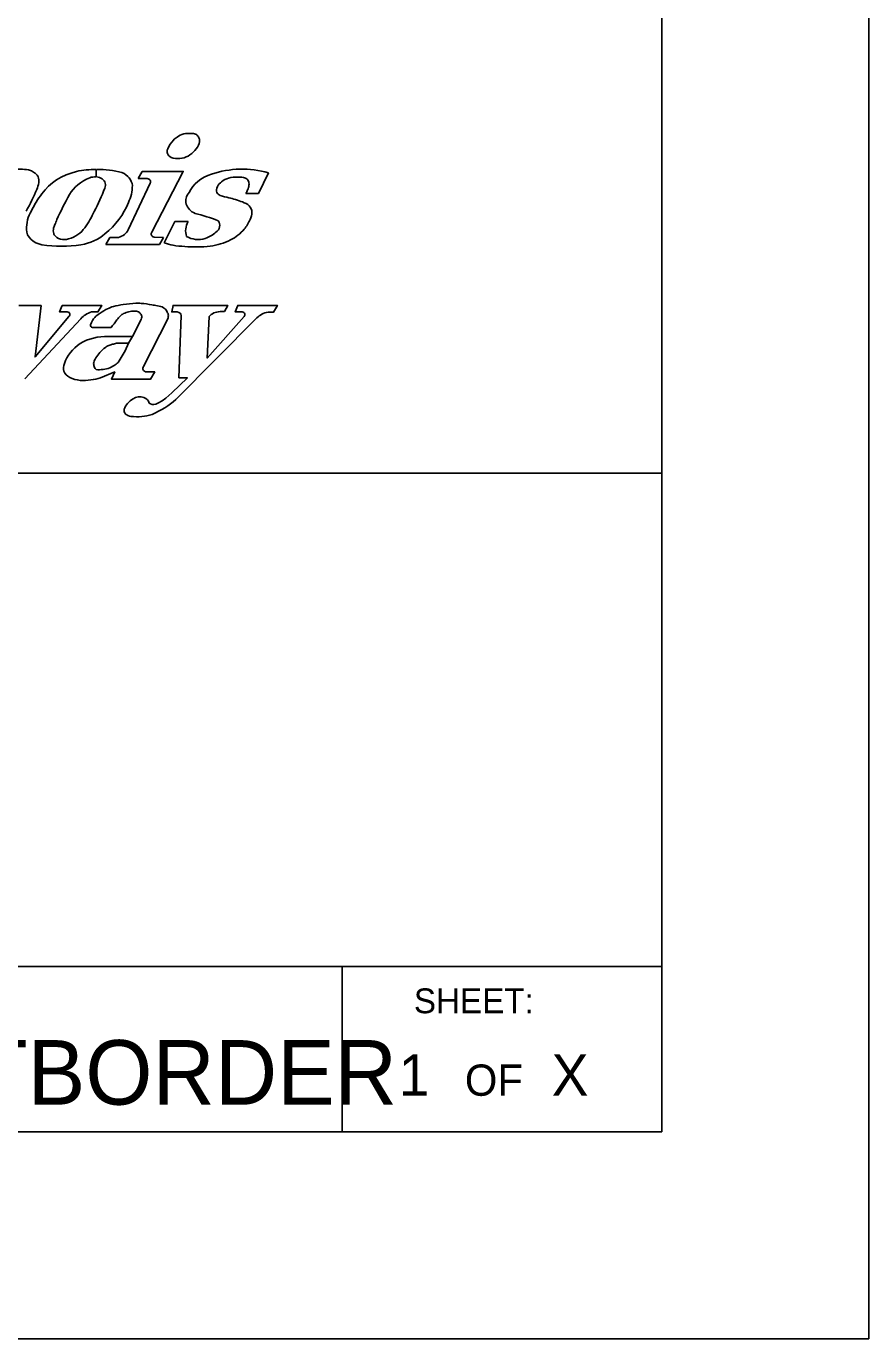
# Model space of a CAD drawing. Extents: x 0 to 2.83, y 0 to 1.83.
# Drawn here: x 2.6636 to 2.8333, y 0 to 0.2643 of the extents above; entities that cross this region are included whole.
import ezdxf

# ---------------------------------------------------------------- set-up
doc = ezdxf.new("R2010")
doc.units = 0
for name, color, linetype in [('SH_General_Details', 7, 'Continuous'), ('SH_General_Details_Sheet_Number-ILTollway', 7, 'Continuous'), ('SH_General_Details_Sheet_Standard-ILTollway', 7, 'Continuous'), ('SH_General_Details_Total_Sheet_Number-ILTollway', 7, 'Continuous'), ('SH_Printer Plotting Border-ILTollway', 7, 'Continuous')]:
    doc.layers.add(name, color=color, linetype=linetype)

msp = doc.modelspace()

# ---------------------------------------------------------------- linework, layer by layer
at = {"layer": 'SH_General_Details'}
for p, q in [((2.677722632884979, 0.23550538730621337), (2.677722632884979, 0.23398690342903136)), ((2.677722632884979, 0.23398690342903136), (2.677722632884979, 0.23550538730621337)), ((2.6885865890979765, 0.2327443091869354), (2.68415580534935, 0.22329691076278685)), ((2.712401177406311, 0.23480902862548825), (2.7104256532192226, 0.2306287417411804)), ((2.7104256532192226, 0.2306287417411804), (2.707885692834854, 0.2306287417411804)), ((2.691431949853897, 0.2207216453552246), (2.693539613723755, 0.22497970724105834)), ((2.693539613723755, 0.22497970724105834), (2.696267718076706, 0.22497970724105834)), ((2.6804911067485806, 0.22181505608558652), (2.679698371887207, 0.22034836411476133)), ((2.679698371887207, 0.22034836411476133), (2.690483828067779, 0.22034499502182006)), ((2.682211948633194, 0.22181223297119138), (2.6804911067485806, 0.22181505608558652)), ((2.6912765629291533, 0.22181168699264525), (2.689411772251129, 0.22182814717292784)), ((2.690483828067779, 0.22034499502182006), (2.6912765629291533, 0.22181168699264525)), ((2.6914229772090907, 0.2207241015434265), (2.691431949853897, 0.2207216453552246)), ((2.6666739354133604, 0.2080908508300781), (2.6621581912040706, 0.2080908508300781)), ((2.663346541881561, 0.19334409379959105), (2.6746359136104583, 0.20542692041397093)), ((2.6807524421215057, 0.20365352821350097), (2.6769743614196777, 0.20365352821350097)), ((2.6850233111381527, 0.20185651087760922), (2.6867754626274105, 0.20527522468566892)), ((2.6921414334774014, 0.20540671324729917), (2.6872682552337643, 0.19580801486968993)), ((2.693792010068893, 0.1891406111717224), (2.710100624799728, 0.20560188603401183)), ((2.6948400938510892, 0.2060494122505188), (2.694351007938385, 0.19350281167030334)), ((2.680150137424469, 0.20185651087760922), (2.6850233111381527, 0.20185651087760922)), ((2.6850233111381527, 0.20185651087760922), (2.684256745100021, 0.20049779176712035)), ((2.684256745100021, 0.20049779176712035), (2.6850233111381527, 0.20185651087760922)), ((2.7916666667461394, 0.17433751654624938), (2.4316674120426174, 0.17433751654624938)), ((2.7916666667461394, 0.07499986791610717), (2.4316674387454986, 0.07499986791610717)), ((2.727257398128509, 0.04166674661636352), (2.7272573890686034, 0.07499992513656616))]:
    msp.add_line(p, q, dxfattribs=at)
msp.add_lwpolyline([(0.1666666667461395, 0.0416666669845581), (0.1666666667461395, 1.791666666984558), (2.7916666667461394, 1.791666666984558), (2.7916666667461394, 0.0416666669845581)], close=True, dxfattribs=at)
for points in [[(2.6869759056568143, 0.2350827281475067), (2.68618249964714, 0.23364955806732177)], [(2.68618249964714, 0.23364955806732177), (2.688017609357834, 0.23364955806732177)], [(2.6889164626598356, 0.22286735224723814), (2.695271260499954, 0.23508543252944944), (2.6869759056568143, 0.2350827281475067)], [(2.672199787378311, 0.20590262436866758), (2.6654261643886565, 0.19772055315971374), (2.6666739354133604, 0.2080908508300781)], [(2.67089259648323, 0.2080908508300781), (2.6703578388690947, 0.20680645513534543), (2.6716650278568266, 0.20680645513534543)], [(2.6767749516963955, 0.20680645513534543), (2.6780821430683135, 0.20680645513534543), (2.6788545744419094, 0.2080908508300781), (2.67089259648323, 0.2080908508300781)], [(2.7026660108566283, 0.2068549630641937), (2.7035604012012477, 0.2068549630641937), (2.7042311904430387, 0.20810803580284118), (2.693219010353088, 0.20810803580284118), (2.6929395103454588, 0.20681020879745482), (2.6940575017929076, 0.20681020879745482)], [(2.7123366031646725, 0.20676545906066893), (2.7134545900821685, 0.20676545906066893), (2.71423718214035, 0.20810803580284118), (2.706243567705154, 0.20810803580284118), (2.705740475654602, 0.20681020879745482), (2.7071379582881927, 0.20681020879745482)], [(2.70752925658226, 0.20587040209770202), (2.7000946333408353, 0.19750165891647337), (2.7004859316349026, 0.20587040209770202)], [(2.684256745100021, 0.20049779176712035), (2.681792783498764, 0.20049779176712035)], [(2.682176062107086, 0.1965969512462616), (2.6835449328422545, 0.19896375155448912), (2.684256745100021, 0.20049779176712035)], [(2.687852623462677, 0.1947122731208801), (2.689513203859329, 0.1947122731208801), (2.6886918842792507, 0.19326589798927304), (2.6808071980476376, 0.19326589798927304), (2.6814642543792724, 0.1947122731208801), (2.6786170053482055, 0.19352887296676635)], [(2.694351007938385, 0.19350281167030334), (2.6961118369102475, 0.19350281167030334), (2.692953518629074, 0.19048282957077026), (2.691723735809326, 0.18940905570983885)]]:
    msp.add_lwpolyline(points, dxfattribs=at)
for centre, major_axis, ratio, start_param, end_param in [((2.6999652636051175, 0.2375553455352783), (-0.008237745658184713, 1.0088328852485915e-18), 0.8000752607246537, 5.657384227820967, 5.961923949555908), ((2.692348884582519, 0.24230186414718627), (0.006436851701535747, -1.5765739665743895e-18), 0.8000752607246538, 5.35994097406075, 5.975474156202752), ((2.6938173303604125, 0.2390981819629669), (-0.00179891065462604, 2.2030301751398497e-19), 0.8000752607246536, 5.899852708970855, 7.2592592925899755), ((2.694211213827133, 0.24040055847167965), (-0.003418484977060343, 4.1864366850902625e-19), 0.800075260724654, 1.1482793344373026, 2.20319774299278), ((2.6778777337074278, 0.2225923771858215), (-0.016140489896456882, 1.9766399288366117e-18), 0.8000752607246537, 4.721998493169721, 4.969094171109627), ((2.6778777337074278, 0.2225923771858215), (-0.016140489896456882, 1.9766399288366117e-18), 0.8000383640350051, 4.395078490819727, 4.7149049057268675), ((2.7071054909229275, 0.22304212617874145), (0.01563161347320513, -3.82864108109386e-18), 0.8000752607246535, 1.2251758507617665, 1.9740563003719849), ((2.677345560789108, 0.22580751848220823), (-0.012129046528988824, 1.4853798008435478e-18), 0.8000752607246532, 5.01078761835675, 5.765691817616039), ((2.6803047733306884, 0.22758793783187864), (-0.008689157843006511, 1.0641149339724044e-18), 0.8000752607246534, 5.175654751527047, 5.860096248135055), ((2.6774772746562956, 0.2320206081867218), (-0.0024698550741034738, 3.024700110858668e-19), 0.8000752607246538, 4.612883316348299, 5.153926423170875), ((2.6774772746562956, 0.2320206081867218), (-0.0024698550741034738, 3.024700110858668e-19), 0.8000752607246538, 4.071840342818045, 4.566171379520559), ((2.6774212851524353, 0.23236350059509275), (0.002180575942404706, -5.340870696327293e-19), 0.8000752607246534, 5.909204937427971, 7.074943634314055), ((2.6809203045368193, 0.23198325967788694), (0.004112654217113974, -1.0073097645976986e-18), 0.8000752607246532, 0.08712246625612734, 1.0647598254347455), ((2.687906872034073, 0.23303792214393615), (0.0007724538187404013, -1.8919661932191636e-19), 0.800075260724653, 5.788124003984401, 7.71013160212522), ((2.703739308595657, 0.22878499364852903), (-0.007713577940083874, 9.44640853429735e-19), 0.8000752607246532, 5.0794162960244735, 5.947658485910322), ((2.6937143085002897, 0.2178005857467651), (-0.03131109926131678, 3.8345037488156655e-18), 0.8000752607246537, 5.7465390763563, 5.900046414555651), ((2.7748348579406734, 0.19390384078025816), (-0.11217070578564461, 1.3736949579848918e-17), 0.8000752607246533, 5.863868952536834, 5.924634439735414), ((2.62606113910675, 0.24434618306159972), (0.0556713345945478, -1.3635544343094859e-17), 0.8000752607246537, 5.883899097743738, 5.995916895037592), ((2.672557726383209, 0.2323223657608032), (0.012459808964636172, -3.051773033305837e-18), 0.8000752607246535, 5.922241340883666, 6.277888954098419), ((2.699367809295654, 0.22914537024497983), (-0.0035839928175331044, 4.389125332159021e-19), 0.8000752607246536, 5.6607938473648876, 7.348319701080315), ((2.665271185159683, 0.233605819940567), (0.019872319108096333, -4.867314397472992e-18), 0.8000752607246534, 5.5091350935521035, 5.976236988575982), ((2.674661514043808, 0.22350584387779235), (-0.01098572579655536, 1.3453633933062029e-18), 0.8000752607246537, 5.853724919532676, 6.297771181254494), ((2.6506869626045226, 0.2350934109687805), (0.028507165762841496, -6.98224186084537e-18), 0.8000752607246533, 5.76243947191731, 5.92185011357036), ((2.7011339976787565, 0.22313573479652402), (-0.005384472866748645, 6.5940774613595e-19), 0.8000752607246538, 5.840866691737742, 6.548879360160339), ((2.6885973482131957, 0.20284208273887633), (0.03108248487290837, -7.613013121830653e-18), 0.8000752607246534, 1.1146700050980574, 1.2758801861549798), ((2.7003394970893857, 0.2242215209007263), (0.0022798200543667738, -5.583948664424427e-19), 0.8000752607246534, 5.41802630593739, 6.828748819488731), ((2.667664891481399, 0.22343681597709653), (-0.0039886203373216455, 4.88465112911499e-19), 0.8000752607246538, 0.018542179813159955, 1.3534190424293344), ((2.6713157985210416, 0.22325227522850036), (-0.002357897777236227, 2.887591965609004e-19), 0.8000752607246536, 0.5153538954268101, 1.9459629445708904), ((2.6701127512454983, 0.22601519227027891), (0.006013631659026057, -1.4729149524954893e-18), 0.8000752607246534, 5.063271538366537, 5.7920136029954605), ((2.672220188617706, 0.22813850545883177), (0.010126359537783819, -2.480242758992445e-18), 0.8000752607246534, 4.9562759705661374, 5.511991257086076), ((2.6813631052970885, 0.22408055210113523), (0.0029594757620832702, -7.2486250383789e-19), 0.8000752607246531, 5.003296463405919, 5.945866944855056), ((2.6897492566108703, 0.22252627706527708), (-0.0009355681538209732, 1.1457405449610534e-19), 0.8000752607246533, 5.810064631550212, 7.484931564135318), ((2.6973413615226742, 0.22593837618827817), (0.005924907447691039, -1.4511837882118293e-18), 0.8000752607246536, 5.122073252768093, 5.568902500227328), ((2.6708979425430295, 0.23879757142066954), (0.023453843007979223, -5.744534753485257e-18), 0.8000752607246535, 4.536965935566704, 4.873723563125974), ((2.698293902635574, 0.22455339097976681), (0.003961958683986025, -9.704000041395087e-19), 0.800075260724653, 4.075728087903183, 5.075565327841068), ((2.6718014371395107, 0.20630493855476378), (-0.0006415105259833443, 7.856238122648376e-20), 0.8000752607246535, 2.240755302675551, 4.926665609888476), ((2.6786161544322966, 0.20322768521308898), (-0.004837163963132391, 5.923817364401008e-19), 0.8000752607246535, 5.102873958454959, 5.678790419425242), ((2.6938554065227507, 0.20603908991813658), (0.0009847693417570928, -2.411989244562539e-19), 0.8000752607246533, 0.013105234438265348, 1.364108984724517), ((2.702730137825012, 0.2047267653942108), (-0.002660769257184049, 3.2585025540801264e-19), 0.8000752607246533, 4.736493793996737, 5.716049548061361), ((2.706971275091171, 0.20624373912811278), (0.0007273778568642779, -1.7815619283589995e-19), 0.8000752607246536, 5.58671279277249, 7.622770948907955), ((2.7134031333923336, 0.20349651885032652), (-0.00422269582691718, 5.171310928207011e-19), 0.800075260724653, 4.967725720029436, 5.610393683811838), ((2.6798079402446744, 0.19477745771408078), (0.00885459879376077, -2.168751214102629e-18), 0.8000752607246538, 1.532140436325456, 2.2138077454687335), ((2.681011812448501, 0.19436913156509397), (-0.010006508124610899, 1.2254438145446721e-18), 0.8000752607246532, 5.421148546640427, 6.024304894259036), ((2.674052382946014, 0.19551704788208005), (-0.0029383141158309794, 3.598396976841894e-19), 0.8000752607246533, 5.889585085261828, 7.258805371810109), ((2.687964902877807, 0.1953982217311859), (-0.000864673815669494, 1.0589200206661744e-19), 0.8000752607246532, 5.649203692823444, 7.723758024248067), ((2.675246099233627, 0.1975628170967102), (-0.005742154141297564, 7.032110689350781e-19), 0.8000752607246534, 1.0532160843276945, 1.8172744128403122), ((2.675063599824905, 0.20100443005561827), (0.009996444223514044, -2.4484226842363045e-18), 0.8000752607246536, 4.871468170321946, 5.075802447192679), ((2.687607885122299, 0.1864386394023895), (-0.004317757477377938, 5.287727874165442e-19), 0.8000752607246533, 5.308575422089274, 6.062627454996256), ((2.686509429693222, 0.18802140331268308), (0.002073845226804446, -5.079455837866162e-19), 0.8000752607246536, 1.1610346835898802, 2.2644571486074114), ((2.686640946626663, 0.18820606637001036), (0.001809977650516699, -4.4331666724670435e-19), 0.8000752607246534, 0.1672490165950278, 1.176879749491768), ((2.6892302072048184, 0.18900743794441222), (0.0010666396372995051, -2.612513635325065e-19), 0.8000752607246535, 3.8578413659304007, 5.180372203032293), ((2.6802619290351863, 0.19916098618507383), (0.018436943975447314, -4.515748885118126e-18), 0.8000752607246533, 5.2052083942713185, 5.536371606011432), ((2.685642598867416, 0.19444732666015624), (0.008754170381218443, -2.1441533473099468e-18), 0.8000752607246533, 5.195774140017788, 5.480330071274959), ((2.684836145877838, 0.18694080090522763), (-0.0014758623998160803, 1.807410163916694e-19), 0.8000752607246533, 6.066729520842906, 7.786283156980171), ((2.6860296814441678, 0.19157500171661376), (-0.007378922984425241, 9.036574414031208e-19), 0.8000752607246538, 1.3946067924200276, 1.9828177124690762)]:
    msp.add_ellipse(centre, major_axis=major_axis, ratio=ratio, start_param=start_param, end_param=end_param, dxfattribs=at)
for points in [[(2.6984833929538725, 0.24074205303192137), (2.698543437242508, 0.24139097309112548), (2.698333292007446, 0.24203988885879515), (2.697732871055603, 0.2426167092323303), (2.6968322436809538, 0.2427609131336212), (2.695361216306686, 0.24264074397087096), (2.6940102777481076, 0.2420158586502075), (2.6932886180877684, 0.24141589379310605)], [(2.6636318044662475, 0.22710824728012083), (2.665756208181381, 0.2314826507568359), (2.6661532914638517, 0.23283391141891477), (2.6660341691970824, 0.23399440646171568), (2.665835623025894, 0.23431235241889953), (2.665279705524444, 0.23483696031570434), (2.664465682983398, 0.23528208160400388), (2.662897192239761, 0.23552054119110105), (2.66228171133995, 0.2355682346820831), (2.6615669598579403, 0.23550464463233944), (2.660038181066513, 0.23528208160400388), (2.657933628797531, 0.23466209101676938), (2.6565209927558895, 0.23410625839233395), (2.6549143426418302, 0.233294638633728)], [(2.707885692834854, 0.2306287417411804), (2.7082149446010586, 0.23138194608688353), (2.708497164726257, 0.23232345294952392), (2.7083560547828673, 0.2332272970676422), (2.7077916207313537, 0.23375454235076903), (2.706239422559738, 0.23394284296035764), (2.7044050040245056, 0.23375454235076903), (2.7029939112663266, 0.2330013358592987), (2.7021472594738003, 0.23202217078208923), (2.702006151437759, 0.23081704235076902), (2.702711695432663, 0.23025214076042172), (2.7044520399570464, 0.2298002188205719), (2.7071801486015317, 0.2289340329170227), (2.7085442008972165, 0.22818082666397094), (2.709108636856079, 0.226825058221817), (2.708732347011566, 0.22543162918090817), (2.707556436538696, 0.22347329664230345), (2.7047812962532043, 0.22128900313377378), (2.700689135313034, 0.22004621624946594), (2.695562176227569, 0.21997089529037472), (2.693210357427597, 0.22023451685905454), (2.6914229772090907, 0.2207241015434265)], [(2.6692641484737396, 0.22232252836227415), (2.669176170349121, 0.22257139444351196), (2.669161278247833, 0.22368050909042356), (2.6694293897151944, 0.22437221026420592), (2.6697974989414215, 0.22539694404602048)], [(2.6769743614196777, 0.20365352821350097), (2.676643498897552, 0.20388088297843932), (2.6767944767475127, 0.20468631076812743), (2.677675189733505, 0.2059145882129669), (2.678555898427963, 0.2065790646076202), (2.6800405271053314, 0.2074448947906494), (2.6811980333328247, 0.2078878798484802), (2.6831607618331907, 0.20827045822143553), (2.6857274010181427, 0.20855235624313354), (2.6868094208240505, 0.20851208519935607), (2.6889231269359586, 0.20823018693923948), (2.690055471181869, 0.20802882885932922), (2.6913136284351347, 0.20764625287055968), (2.691665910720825, 0.20732408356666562), (2.6919427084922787, 0.20692136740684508), (2.692244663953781, 0.2062971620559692), (2.6921414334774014, 0.20540671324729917)], [(2.6867754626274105, 0.20527522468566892), (2.68691007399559, 0.20575349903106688), (2.6866836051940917, 0.20641797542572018), (2.6862306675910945, 0.2068005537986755), (2.685450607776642, 0.20696164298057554), (2.6842931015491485, 0.20682068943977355), (2.683236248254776, 0.20645824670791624), (2.682607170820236, 0.20601526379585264), (2.681902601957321, 0.2051695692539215), (2.6807524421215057, 0.20365352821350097)], [(2.681792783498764, 0.20049779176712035), (2.681041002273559, 0.20027854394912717), (2.6802609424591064, 0.20005705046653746), (2.6795815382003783, 0.19965433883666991), (2.678449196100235, 0.1986072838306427), (2.6776691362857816, 0.197519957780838), (2.677241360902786, 0.19663399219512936), (2.677316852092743, 0.19578829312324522), (2.67751815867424, 0.19538557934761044), (2.678751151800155, 0.19518422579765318), (2.680135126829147, 0.1954258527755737), (2.681368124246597, 0.19602992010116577), (2.682176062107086, 0.1965969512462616)]]:
    msp.add_spline(points, degree=3, dxfattribs=at)
at = {"layer": 'SH_Printer Plotting Border-ILTollway'}
msp.add_lwpolyline([(0, 1.833282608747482), (2.833327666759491, 1.833282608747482), (2.833327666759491, 0), (0, 0)], close=True, dxfattribs=at)

# ---------------------------------------------------------------- texts
at = {"layer": 'SH_General_Details'}
for s, height, p in [('SHEET:', 0.004999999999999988, (2.7417119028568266, 0.06555551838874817)), ('OF', 0.0062999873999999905, (2.751983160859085, 0.04893333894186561))]:
    msp.add_text(s, height=height, rotation=1.0784289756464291e-05, dxfattribs=at).set_placement(p)
at = {"layer": 'SH_General_Details_Sheet_Number-ILTollway'}
msp.add_text('1', height=0.008333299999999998, rotation=1.0784289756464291e-05, dxfattribs=at).set_placement((2.738644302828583, 0.04893335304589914))
at = {"layer": 'SH_General_Details_Sheet_Standard-ILTollway'}
msp.add_text('STANDARDSHEETBORDER', height=0.013, dxfattribs=at).set_placement((2.510364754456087, 0.047145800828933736))
at = {"layer": 'SH_General_Details_Total_Sheet_Number-ILTollway'}
msp.add_text('X', height=0.008333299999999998, rotation=1.0784289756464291e-05, dxfattribs=at).set_placement((2.769456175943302, 0.048933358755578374))

doc.saveas('drawing.dxf')
